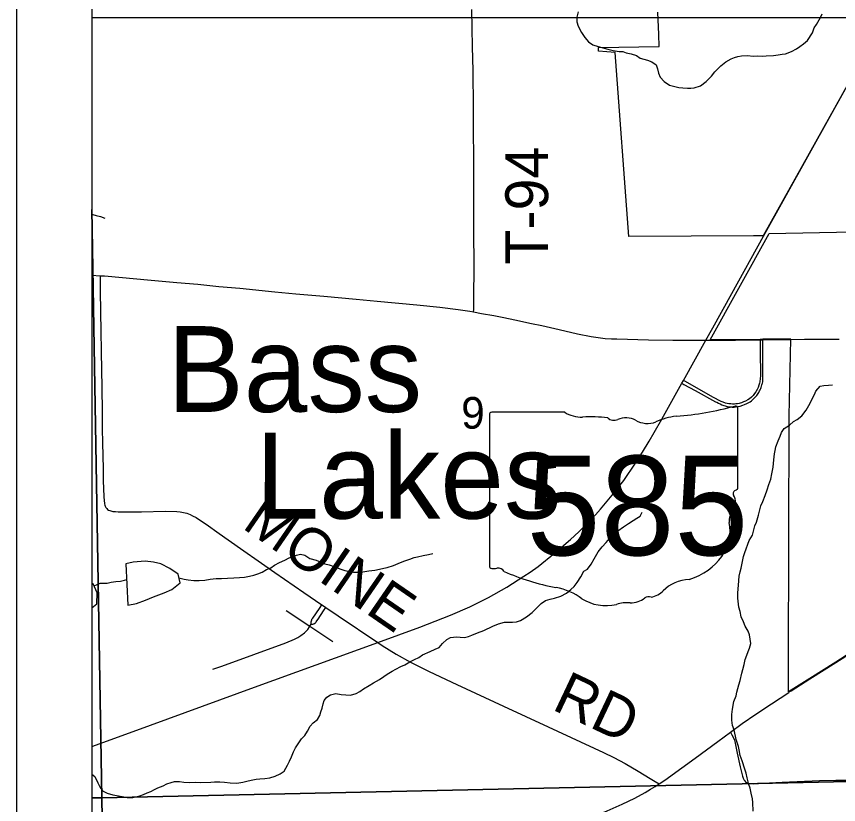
# Model space of a CAD drawing. Extents: x 0 to 34, y -5 to 22.
# Drawn here: x 2 to 3.09, y 14.575 to 15.62 of the extents above; entities that cross this region are included whole.
import ezdxf

# ---------------------------------------------------------------- set-up
doc = ezdxf.new("R2010")
doc.units = 0
for name, color, linetype in [('GM_X_City_Street', 7, 'Continuous'), ('GM_X_Corporation', 7, 'Continuous'), ('GM_X_County_Road', 7, 'Continuous'), ('GM_X_Interchange_Ramps', 7, 'Continuous'), ('GM_X_Minor_Lake', 7, 'Continuous'), ('GM_X_Minor_Lake_Text', 7, 'Continuous'), ('GM_X_Minor_River', 7, 'Continuous'), ('GM_X_Section_Text', 7, 'Continuous'), ('GM_X_State_Location', 7, 'Continuous'), ('GM_X_State_Route', 7, 'Continuous'), ('GM_X_State_Shield', 7, 'Continuous'), ('GM_X_Township_Road', 7, 'Continuous'), ('GM_X_Township_Road_Text', 7, 'Continuous'), ('GM_X_US_Route', 7, 'Continuous'), ('SH_Cut_Line', 7, 'Continuous'), ('SH_Data', 7, 'Continuous')]:
    doc.layers.add(name, color=color, linetype=linetype)

msp = doc.modelspace()

# ---------------------------------------------------------------- linework, layer by layer
at = {"layer": 'GM_X_City_Street'}
for points in [[(2.1, 15.6177), (2.1, 15.3638), (2.1133, 14.5841), (3.104, 14.6056), (3.1044, 15.6177)], [(2.1, 15.3638), (2.1, 14.584), (2.1133, 14.5841)], [(2.1212, 14.1), (3.1115, 14.1), (3.104, 14.6056), (2.1133, 14.5841)], [(2.1, 14.584), (2.1, 14.1), (2.1212, 14.1), (2.1133, 14.5841)]]:
    msp.add_lwpolyline(points, close=True, dxfattribs=at)
at = {"layer": 'GM_X_Corporation'}
for points in [[(3.1122, 15.5472), (2.9904, 15.3289), (2.9775, 15.3288), (2.8119, 15.3279), (2.794, 15.572), (2.772, 15.5737), (2.7719, 15.5784), (2.8525, 15.5797), (2.8518, 15.5958), (2.8506, 15.6253)], [(3.1414, 14.7989), (3.0864, 14.7636), (3.0521, 14.7421), (3.0239, 14.7242), (3.024, 14.7616), (3.0246, 15.0904), (3.027, 15.192), (2.9897, 15.1916), (2.9862, 15.1915), (2.9198, 15.1909), (2.9981, 15.3319), (3.1097, 15.3342)]]:
    msp.add_lwpolyline(points, dxfattribs=at)
at = {"layer": 'GM_X_County_Road'}
for p, q in [((2.1, 15.2766), (2.111, 15.2759)), ((2.9864, 15.191), (2.9899, 15.191)), ((2.9899, 15.191), (3.0273, 15.1915)), ((3.0249, 14.7242), (3.0274, 14.7258))]:
    msp.add_line(p, q, dxfattribs=at)
for points in [[(2.111, 15.2759), (2.1168, 15.2756), (2.1787, 15.2701), (2.2128, 15.2671), (2.2406, 15.2645), (2.2685, 15.2618), (2.2963, 15.2592), (2.3427, 15.2547), (2.3705, 15.2521), (2.4075, 15.2486), (2.4507, 15.2449), (2.4785, 15.2424), (2.5308, 15.2374), (2.5616, 15.2344), (2.5857, 15.2312), (2.6014, 15.2288), (2.6063, 15.2279)], [(2.6063, 15.2279), (2.6169, 15.226), (2.6331, 15.223), (2.6461, 15.2205), (2.6608, 15.2175), (2.6832, 15.2128), (2.6967, 15.2098), (2.708, 15.2071), (2.7195, 15.2045), (2.7438, 15.1991), (2.762, 15.1954), (2.7713, 15.1939), (2.7806, 15.1929), (2.789, 15.1922), (2.7961, 15.1921), (2.8383, 15.191), (2.8706, 15.1904), (2.8892, 15.1903), (2.9103, 15.1903)], [(2.9103, 15.1903), (2.9144, 15.1904), (2.9491, 15.1905)], [(2.9491, 15.1905), (2.9534, 15.1906), (2.9812, 15.1909), (2.9864, 15.191)], [(3.0273, 15.1915), (3.0452, 15.1918), (3.0908, 15.1919)], [(3.0274, 14.7258), (3.0523, 14.7416), (3.0866, 14.7631), (3.1416, 14.7983), (3.1707, 14.8168), (3.2181, 14.847), (3.2417, 14.862), (3.2546, 14.8707), (3.2607, 14.8748), (3.2724, 14.8838), (3.2854, 14.8947), (3.2861, 14.8954)], [(2.9469, 14.671), (2.9625, 14.6824), (2.9804, 14.6949), (3.0012, 14.7085), (3.0241, 14.7237), (3.0249, 14.7242)], [(2.8521, 14.6023), (2.8597, 14.6074), (2.8823, 14.6237), (2.8999, 14.6365), (2.9299, 14.6586), (2.9469, 14.671)], [(2.841, 14.5953), (2.8468, 14.5988), (2.8521, 14.6023)], [(2.6174, 14.5186), (2.6591, 14.5285), (2.6954, 14.5371), (2.7164, 14.5427), (2.7341, 14.5482), (2.7517, 14.5542), (2.7692, 14.5608), (2.7835, 14.5665), (2.8033, 14.5754), (2.82, 14.5835), (2.8336, 14.5909), (2.841, 14.5953)]]:
    msp.add_lwpolyline(points, dxfattribs=at)
at = {"layer": 'GM_X_Interchange_Ramps'}
for points in [[(2.8822, 15.1334), (2.885, 15.1319), (2.9, 15.124), (2.9271, 15.1089), (2.9287, 15.1081), (2.9309, 15.1069), (2.9331, 15.1059), (2.9355, 15.1049), (2.9382, 15.1039), (2.9398, 15.1034), (2.9413, 15.103), (2.9426, 15.1027), (2.9452, 15.1022), (2.9475, 15.102), (2.949, 15.1019), (2.9516, 15.1019), (2.9537, 15.102), (2.9569, 15.1024), (2.9598, 15.1031), (2.9631, 15.1042), (2.9656, 15.1052), (2.9684, 15.1064), (2.9712, 15.1079), (2.9728, 15.1088), (2.9748, 15.1103), (2.9762, 15.1115), (2.9787, 15.1139), (2.9806, 15.1159), (2.9817, 15.1173), (2.9826, 15.1185), (2.9835, 15.1198), (2.9844, 15.1211), (2.985, 15.1221), (2.9855, 15.1232), (2.9862, 15.1245), (2.9871, 15.1265), (2.9877, 15.1279), (2.9882, 15.1297), (2.9886, 15.1312), (2.989, 15.1326), (2.9893, 15.1337), (2.9896, 15.1354), (2.9898, 15.137), (2.9899, 15.139), (2.9898, 15.1698), (2.9899, 15.1877), (2.9899, 15.191)], [(2.9864, 15.191), (2.9863, 15.1877), (2.9862, 15.1768), (2.9865, 15.1428), (2.9864, 15.14), (2.9863, 15.1384), (2.986, 15.1366), (2.9857, 15.1352), (2.9853, 15.1335), (2.9844, 15.1307), (2.9834, 15.1279), (2.9821, 15.1249), (2.9804, 15.1221), (2.9788, 15.1196), (2.9768, 15.1171), (2.9746, 15.1149), (2.9723, 15.1129), (2.9698, 15.1112), (2.9669, 15.1097), (2.9642, 15.1086), (2.9616, 15.1075), (2.9599, 15.1069), (2.9582, 15.1065), (2.9562, 15.1061), (2.9539, 15.1059), (2.9523, 15.1058), (2.9496, 15.1058), (2.9475, 15.1059), (2.9448, 15.1062), (2.9426, 15.1066), (2.9401, 15.1072), (2.9373, 15.1081), (2.9343, 15.1093), (2.9233, 15.115), (2.887, 15.1357), (2.8844, 15.1372)]]:
    msp.add_lwpolyline(points, dxfattribs=at)
at = {"layer": 'GM_X_Minor_Lake'}
for points in [[(2.1479, 14.8392), (2.1592, 14.8416), (2.1713, 14.8458), (2.1819, 14.8505), (2.1959, 14.8555), (2.2061, 14.8598), (2.217, 14.869), (2.2143, 14.8803), (2.2036, 14.8879), (2.1914, 14.8942), (2.1816, 14.8964), (2.1706, 14.8975), (2.155, 14.8962), (2.1452, 14.8939)], [(2.1452, 14.8939), (2.1479, 14.8392)], [(2.1, 14.8355), (2.1065, 14.8411), (2.1072, 14.8556), (2.1018, 14.8677), (2.1, 14.8684)]]:
    msp.add_lwpolyline(points, dxfattribs=at)
at = {"layer": 'GM_X_Minor_River'}
for points in [[(2.7447, 15.6255), (2.743, 15.6186), (2.7431, 15.6125), (2.7447, 15.6068), (2.7491, 15.5985), (2.7538, 15.5918), (2.7588, 15.5861), (2.7642, 15.5821), (2.7715, 15.5799), (2.7795, 15.5774), (2.7841, 15.5764), (2.7914, 15.5746), (2.7994, 15.5732), (2.804, 15.5733), (2.8086, 15.5715), (2.8151, 15.5701), (2.8224, 15.5676), (2.827, 15.5642), (2.8369, 15.5618), (2.8427, 15.5596), (2.8481, 15.5555), (2.8501, 15.5502), (2.8514, 15.5445), (2.8538, 15.5389), (2.8588, 15.5333), (2.8661, 15.5285), (2.8711, 15.527), (2.8784, 15.5256), (2.8837, 15.525), (2.8898, 15.5247), (2.8944, 15.5244), (2.8989, 15.5249), (2.9073, 15.5277), (2.9148, 15.5332), (2.9219, 15.5406), (2.9263, 15.546), (2.9342, 15.5541), (2.9405, 15.5596), (2.9477, 15.5635), (2.9522, 15.5651)], [(2.9522, 15.5651), (2.9568, 15.5663), (2.9613, 15.5672), (2.9693, 15.5677), (2.9769, 15.5671), (2.9826, 15.5672), (2.9891, 15.567), (2.9944, 15.5674), (3.0039, 15.568), (3.01, 15.5685), (3.0153, 15.5694), (3.0199, 15.5702), (3.0278, 15.573), (3.0342, 15.5766), (3.0387, 15.5797), (3.0436, 15.5832), (3.0492, 15.5879), (3.0555, 15.5979), (3.058, 15.6044), (3.061, 15.6091), (3.0661, 15.6183), (3.0683, 15.6229)], [(2.1, 15.3573), (2.1013, 15.357), (2.1059, 15.3556), (2.1113, 15.3542), (2.117, 15.3524)], [(2.9664, 14.8115), (2.964, 14.8172), (2.9612, 14.8236), (2.9596, 14.8308), (2.958, 14.8365), (2.9566, 14.8486), (2.9564, 14.8555), (2.9574, 14.8658), (2.9583, 14.8779), (2.9597, 14.8833), (2.9611, 14.8883), (2.9643, 14.9036), (2.9657, 14.9089), (2.9715, 14.925), (2.9759, 14.9319), (2.9791, 14.9446), (2.9813, 14.9492), (2.9841, 14.9587), (2.9869, 14.971), (2.9899, 14.9767), (2.9928, 14.9844), (2.9953, 14.9921), (2.9978, 14.9993), (3.0003, 15.0062), (3.0017, 15.0135), (3.0035, 15.0223), (3.0041, 15.0272), (3.0044, 15.0318), (3.0054, 15.0398), (3.0061, 15.0444), (3.0071, 15.049), (3.01, 15.057), (3.0126, 15.0632), (3.0147, 15.0682), (3.0181, 15.0736), (3.0252, 15.0779), (3.0304, 15.0829), (3.0354, 15.0853), (3.0413, 15.09), (3.0473, 15.0977), (3.0524, 15.1069), (3.055, 15.1127), (3.0583, 15.1185), (3.0601, 15.1231), (3.0657, 15.1296), (3.0706, 15.1305), (3.0767, 15.131), (3.082, 15.1311)], [(2.4023, 14.693), (2.4038, 14.698), (2.4052, 14.7026), (2.4066, 14.7083), (2.408, 14.7129), (2.4118, 14.7175), (2.4163, 14.7203), (2.4235, 14.7223), (2.4307, 14.7209), (2.4368, 14.7203), (2.4429, 14.72), (2.4505, 14.7221), (2.4554, 14.7248), (2.4603, 14.7284), (2.4678, 14.7327), (2.4734, 14.7362), (2.4813, 14.7409), (2.487, 14.7445), (2.4915, 14.7476), (2.4983, 14.7519), (2.5032, 14.7543), (2.5099, 14.7578), (2.5152, 14.7602), (2.5216, 14.7642), (2.528, 14.7673), (2.5337, 14.7701), (2.5386, 14.7732), (2.5488, 14.778), (2.5552, 14.7808), (2.5605, 14.7832), (2.5649, 14.7886), (2.5709, 14.7936), (2.5754, 14.7964), (2.5834, 14.7973), (2.5884, 14.797), (2.5941, 14.7964), (2.5994, 14.7976), (2.6039, 14.7996), (2.6115, 14.8024), (2.6198, 14.8056), (2.6319, 14.8112), (2.6394, 14.8147), (2.647, 14.8168), (2.6519, 14.8165), (2.6576, 14.8166), (2.663, 14.8171), (2.6682, 14.8191), (2.6765, 14.8238), (2.684, 14.8297), (2.6896, 14.8351), (2.696, 14.8413), (2.7016, 14.8456), (2.7077, 14.8473), (2.7137, 14.8485), (2.7221, 14.851), (2.7296, 14.8553), (2.7352, 14.86), (2.7397, 14.8642), (2.7434, 14.8693), (2.7486, 14.877), (2.7526, 14.8843), (2.7571, 14.887), (2.762, 14.8936), (2.766, 14.9005), (2.7715, 14.9098), (2.7767, 14.9167), (2.782, 14.9221), (2.7864, 14.9275), (2.7913, 14.9326), (2.7973, 14.9376), (2.8048, 14.9431), (2.8115, 14.9474), (2.8176, 14.9514), (2.8228, 14.9545), (2.8273, 14.9573), (2.8299, 14.9626)], [(2.2155, 14.8754), (2.2222, 14.8737), (2.2279, 14.8727), (2.2352, 14.8721), (2.2424, 14.8718), (2.2496, 14.8724), (2.2569, 14.8736), (2.2648, 14.8745), (2.2721, 14.8747), (2.28, 14.8752), (2.2884, 14.8754), (2.2956, 14.8759), (2.3025, 14.8764), (2.3089, 14.8777), (2.3146, 14.8789), (2.3203, 14.8806), (2.326, 14.8829), (2.3316, 14.8865), (2.3373, 14.8889), (2.3421, 14.8924), (2.3489, 14.8956), (2.3561, 14.8987), (2.3617, 14.9019), (2.3712, 14.9055), (2.3765, 14.9068), (2.3826, 14.9057), (2.3892, 14.9013), (2.3976, 14.8988), (2.4091, 14.8941)], [(2.4091, 14.8941), (2.4145, 14.8926), (2.4221, 14.8901), (2.4302, 14.8868), (2.4355, 14.885), (2.447, 14.883), (2.4523, 14.8831), (2.4592, 14.8836), (2.4675, 14.8849), (2.4751, 14.8858), (2.4816, 14.8871), (2.4872, 14.8883), (2.4918, 14.8892), (2.5001, 14.892), (2.5092, 14.896), (2.5152, 14.898), (2.5216, 14.9004), (2.5273, 14.9024), (2.5319, 14.9033), (2.5394, 14.9049), (2.5466, 14.9066), (2.552, 14.9078)], [(2.103, 14.8649), (2.1112, 14.8682), (2.1203, 14.8684), (2.1256, 14.8696), (2.1317, 14.8705), (2.1378, 14.871), (2.1431, 14.8722), (2.1462, 14.8731)], [(2.9769, 14.5663), (2.9767, 14.5777), (2.9762, 14.5826), (2.9745, 14.5902), (2.9729, 14.5966), (2.9713, 14.6015), (2.9692, 14.6102), (2.9675, 14.6167), (2.9659, 14.622), (2.9623, 14.6329), (2.9599, 14.6398), (2.9586, 14.6473), (2.9573, 14.6519), (2.9545, 14.6613), (2.9516, 14.6742), (2.9496, 14.6799), (2.9487, 14.6867), (2.9485, 14.6943), (2.9495, 14.7016), (2.9512, 14.7115), (2.9545, 14.7192), (2.9552, 14.7238), (2.958, 14.7337), (2.9595, 14.7394), (2.9619, 14.749), (2.9634, 14.754), (2.9648, 14.7605), (2.9665, 14.7674), (2.9687, 14.7731), (2.9705, 14.7777), (2.9719, 14.7823), (2.9737, 14.7884), (2.972, 14.7998), (2.9704, 14.8047), (2.9664, 14.8115)], [(2.1, 14.6151), (2.104, 14.6123), (2.1079, 14.6036), (2.1111, 14.5976), (2.1142, 14.5931), (2.1204, 14.5902), (2.128, 14.588), (2.1353, 14.5866), (2.1402, 14.5856), (2.1467, 14.5842), (2.1544, 14.5844), (2.1635, 14.5864), (2.1687, 14.5884), (2.1733, 14.5904), (2.1782, 14.5924), (2.1831, 14.5948), (2.1876, 14.5972), (2.1944, 14.6), (2.1993, 14.6023), (2.205, 14.6043), (2.2095, 14.6056), (2.2164, 14.6057), (2.2221, 14.6047), (2.2297, 14.6041), (2.2373, 14.6046), (2.2442, 14.6043), (2.2579, 14.6046), (2.2628, 14.6051), (2.2697, 14.6052), (2.2758, 14.6046), (2.2834, 14.6036), (2.2922, 14.6034), (2.3001, 14.6047), (2.3054, 14.6059), (2.3111, 14.6075), (2.3179, 14.6088), (2.3229, 14.6089), (2.3293, 14.6094), (2.3362, 14.6103), (2.343, 14.6127), (2.3498, 14.6159), (2.355, 14.6194), (2.3595, 14.6271), (2.362, 14.6325), (2.3646, 14.6382), (2.3675, 14.6448), (2.37, 14.6501), (2.3745, 14.6567), (2.3782, 14.6621), (2.3823, 14.6667), (2.386, 14.6721), (2.3893, 14.6787), (2.3934, 14.6833), (2.3994, 14.6876), (2.4023, 14.693)]]:
    msp.add_lwpolyline(points, dxfattribs=at)
at = {"layer": 'GM_X_State_Route'}
for points in [[(2.9906, 15.3283), (3.0799, 15.4886), (3.1124, 15.5466)], [(2.8822, 15.1334), (2.8844, 15.1372), (2.9144, 15.1904), (2.9235, 15.2069), (2.9485, 15.2522), (2.9906, 15.3283)], [(2.4791, 14.7897), (2.5349, 14.81), (2.5755, 14.8258), (2.6011, 14.8369), (2.626, 14.8495), (2.6503, 14.8633), (2.6729, 14.8777), (2.6811, 14.8831), (2.6917, 14.8906), (2.7136, 14.908), (2.7347, 14.9264), (2.7456, 14.9366), (2.7608, 14.9516), (2.7677, 14.959), (2.7743, 14.9663), (2.7901, 14.9849), (2.8053, 15.0045), (2.8211, 15.0276), (2.8302, 15.0422), (2.839, 15.0567), (2.8457, 15.0682), (2.8557, 15.086), (2.8822, 15.1334)], [(2.1, 14.652), (2.155, 14.672), (2.3157, 14.7305), (2.4791, 14.7897)]]:
    msp.add_lwpolyline(points, dxfattribs=at)
at = {"layer": 'GM_X_State_Shield'}
for p, q in [((2.9568, 14.9952), (2.9568, 15.0998)), ((2.6272, 15.0914), (2.6272, 14.8913)), ((2.727, 15.0949), (2.6305, 15.0949)), ((2.9568, 14.9952), (2.9568, 14.9952))]:
    msp.add_line(p, q, dxfattribs=at)
for centre, major_axis, start_param, end_param in [((2.8394, 15.3677), (0.3495, 0), 4.814394, 5.042369), ((2.9531, 15.1003), (0.00367, 0), 6.141152, 7.989035), ((2.631, 15.0919), (0.00382, 0), 1.712693, 3.28349), ((2.75, 15.1181), (0.037, 0), 4.042523, 4.731795), ((2.7622, 14.9825), (0.133, 0), 1.404758, 1.657858), ((2.8081, 15.0698), (0.0222, 0), 0.950623, 2.079405), ((2.884, 15.0338), (0.0703, 0), 1.699011, 2.107814), ((2.7924, 15.0929), (0.0107, 0), 3.836095, 5.185415), ((2.8368, 15.1015), (0.0267, 0), 4.081561, 5.145723), ((2.956, 14.9875), (0.00568, 0), 1.883978, 3.671073), ((2.9529, 14.9948), (0.00393, 0), 5.05454, 6.418171), ((2.9198, 14.9742), (0.0341, 0), 5.934695, 6.695948), ((2.9699, 14.9514), (0.0248, 0), 2.387724, 3.262537), ((2.859, 14.938), (0.0874, 0), 5.101752, 6.440018), ((2.631, 14.8909), (0.00385, 0), 3.00124, 4.508301), ((2.6316, 14.9114), (0.0294, 0), 4.665946, 4.897461), ((2.6376, 14.8798), (0.0106, 0), 0.519207, 1.627899), ((2.7714, 15.0596), (0.2524, 0), 4.195997, 4.488961), ((2.8958, 14.8351), (0.0479, 0), 1.647645, 2.488434), ((2.6962, 14.8014), (0.079, 0), 0.823519, 1.323587), ((2.8142, 14.8638), (0.0267, 0), 4.691044, 5.507374), ((2.8384, 14.8444), (0.00752, 0), 1.147584, 2.315152), ((2.8352, 14.8719), (0.0282, 0), 4.937069, 5.64225), ((2.7816, 14.8788), (0.0501, 0), 4.026481, 4.996735), ((2.8106, 14.8096), (0.0412, 0), 1.495662, 1.94098)]:
    msp.add_ellipse(centre, major_axis=major_axis, ratio=0.8, start_param=start_param, end_param=end_param, dxfattribs=at)
at = {"layer": 'GM_X_Township_Road'}
msp.add_line((2.4268, 14.825), (2.4791, 14.7897), dxfattribs=at)
for points in [[(2.6063, 15.2279), (2.6064, 15.2311), (2.6065, 15.2377), (2.6066, 15.2501), (2.6068, 15.2842), (2.6067, 15.3401), (2.6067, 15.3711), (2.6066, 15.4021), (2.606, 15.4984), (2.6055, 15.5481), (2.6049, 15.5792), (2.6037, 15.6288)], [(2.111, 15.2759), (2.111, 15.2713), (2.1111, 15.2558), (2.1115, 15.2279), (2.1128, 15.1502), (2.1132, 15.1285), (2.1136, 15.0945), (2.1138, 15.0728), (2.1141, 15.0542), (2.1148, 15.0201), (2.1152, 15.0046), (2.1158, 14.9828), (2.1167, 14.9734), (2.1171, 14.9719), (2.1178, 14.9703), (2.1186, 14.9689), (2.1197, 14.9675), (2.1207, 14.9662), (2.1222, 14.9652), (2.1239, 14.9646), (2.1253, 14.9642), (2.1277, 14.9636), (2.1312, 14.9633), (2.1349, 14.9631), (2.166, 14.9631), (2.1971, 14.9639), (2.2125, 14.9635), (2.2173, 14.963), (2.2215, 14.9621), (2.2259, 14.961), (2.2302, 14.9593), (2.2336, 14.9578), (2.2384, 14.9553), (2.2442, 14.9516), (2.2514, 14.9468), (2.269, 14.9341), (2.2969, 14.9144), (2.3249, 14.8948), (2.3428, 14.8824), (2.3811, 14.8561), (2.4049, 14.8398)], [(2.3909, 14.8139), (2.3908, 14.8149), (2.3908, 14.816), (2.391, 14.8173), (2.3912, 14.8185), (2.3915, 14.8196), (2.3919, 14.8205), (2.3929, 14.822), (2.4017, 14.8349), (2.4049, 14.8398)], [(2.4049, 14.8398), (2.4073, 14.8382), (2.4102, 14.8362), (2.4268, 14.825)], [(2.2606, 14.7543), (2.2723, 14.7586), (2.3573, 14.7893), (2.3689, 14.794), (2.373, 14.7962), (2.3771, 14.7989), (2.382, 14.8026), (2.3843, 14.8047), (2.3863, 14.8072), (2.3886, 14.8105), (2.3892, 14.8114), (2.3909, 14.8139), (2.3919, 14.814), (2.3931, 14.8142), (2.3938, 14.8144), (2.3944, 14.8146), (2.3955, 14.8153), (2.3961, 14.8156), (2.3968, 14.8163), (2.3976, 14.8172), (2.3985, 14.8186), (2.4002, 14.8209), (2.4073, 14.8317), (2.4102, 14.8362)], [(2.3577, 14.832), (2.3892, 14.8114), (2.3902, 14.8107), (2.4196, 14.7913)], [(2.4791, 14.7897), (2.4848, 14.7858), (2.5034, 14.7743), (2.5224, 14.7638), (2.5475, 14.7513), (2.584, 14.7342), (2.6459, 14.7054), (2.7049, 14.6779), (2.7783, 14.6439), (2.7923, 14.6372), (2.807, 14.6295), (2.8246, 14.6192), (2.8404, 14.6096), (2.8469, 14.6056), (2.8521, 14.6023)], [(2.8521, 14.6023), (2.8597, 14.6074), (2.8823, 14.6237), (2.8999, 14.6365), (2.9299, 14.6586), (2.9469, 14.671)], [(2.9469, 14.671), (2.9487, 14.6676), (2.9504, 14.6641), (2.952, 14.6602), (2.9525, 14.6585), (2.9556, 14.643), (2.9595, 14.6249), (2.9627, 14.6128), (2.9633, 14.6113), (2.9639, 14.6099), (2.9652, 14.6075), (2.9661, 14.6064), (2.967, 14.6053), (2.9683, 14.6044), (2.9696, 14.6037), (2.9707, 14.6033), (2.972, 14.603), (2.9746, 14.6027), (2.9779, 14.6025), (2.9904, 14.6032), (3.0152, 14.6045), (3.0648, 14.6068), (3.0867, 14.6071), (3.1147, 14.6075)]]:
    msp.add_lwpolyline(points, dxfattribs=at)
at = {"layer": 'GM_X_US_Route'}
msp.add_lwpolyline([(2.1, 16.5221), (2.1, 14.1), (6.156, 14.1)], dxfattribs=at)
at = {"layer": 'SH_Cut_Line'}
msp.add_lwpolyline([(2.1, 16.5221), (2.1, 14.1), (6.156, 14.1)], dxfattribs=at)
at = {"layer": 'SH_Data'}
for p, q in [((2, 21), (2, 14)), ((2.1, 20.9), (2.1, 14.1))]:
    msp.add_line(p, q, dxfattribs=at)

# ---------------------------------------------------------------- texts
at = {"layer": 'GM_X_Minor_Lake_Text'}
for s, rotation, p in [('Bass', 359.9828, (2.2, 15.0954)), ('Lakes', 359.983, (2.3169, 14.9541))]:
    msp.add_text(s, height=0.11367, rotation=rotation, dxfattribs=at).set_placement(p)
at = {"layer": 'GM_X_Section_Text'}
msp.add_text('9', height=0.0419, rotation=0, dxfattribs=at).set_placement((2.5898, 15.0732))
at = {"layer": 'GM_X_State_Location'}
for s in ['s', 'r']:
    msp.add_text(s, height=0.000189, dxfattribs=at).set_placement((2.7883, 14.9781))
msp.add_text('585', height=0.000189, rotation=0, dxfattribs=at).set_placement((2.7214, 14.9643))
at = {"layer": 'GM_X_State_Shield'}
msp.add_text('585', height=0.13184, dxfattribs=at).set_placement((2.6764, 14.9054))
at = {"layer": 'GM_X_Township_Road_Text'}
for s, rotation, p in [('T-94', 90, (2.7051, 15.2907)), ('MOINE', 325.4477, (2.2977, 14.9423)), ('RD', 334.7441, (2.7085, 14.7017))]:
    msp.add_text(s, height=0.05682, rotation=rotation, dxfattribs=at).set_placement(p)

doc.saveas('drawing.dxf')
